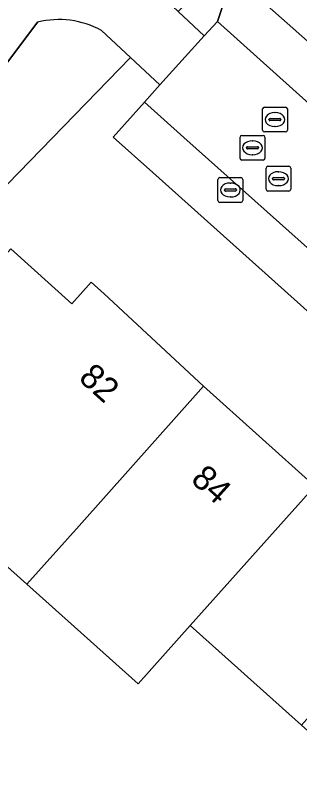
# Model space of a CAD drawing. Extents: x 159039 to 160102, y 381214 to 382524.
# Drawn here: x 159476.76 to 159488.23, y 381770.5 to 381801.71 of the extents above; entities that cross this region are included whole.
import ezdxf

# ---------------------------------------------------------------- set-up
doc = ezdxf.new("R2010")
doc.units = 0
for name, color, linetype in [('IMGEO_Brandkraan', 7, 'Continuous'), ('IMGEO_Erf', 7, 'Continuous'), ('IMGEO_Groenvoorziening', 7, 'Continuous'), ('IMGEO_Pand', 7, 'Continuous'), ('IMGEO_Pand_nummerreeks', 7, 'Continuous'), ('IMGEO_Rijbaan_lokaal_open', 7, 'Continuous'), ('IMGEO_Rioolput', 7, 'Continuous'), ('IMGEO_Voetpad_gesloten', 7, 'Continuous'), ('IMGEO_Voetpad_open', 7, 'Continuous')]:
    doc.layers.add(name, color=color, linetype=linetype)

msp = doc.modelspace()

# ---------------------------------------------------------------- linework, layer by layer
at = {"layer": 'IMGEO_Brandkraan'}
for p, q in [((159484.937, 381794.247), (159484.937, 381795.099)), ((159485.012, 381795.173), (159485.864, 381795.173)), ((159485.425, 381794.953), (159485.45, 381794.953)), ((159485.938, 381795.099), (159485.938, 381794.247)), ((159485.196, 381794.667), (159485.196, 381794.679)), ((159485.634, 381794.63), (159485.236, 381794.63)), ((159485.239, 381794.716), (159485.637, 381794.716)), ((159485.68, 381794.679), (159485.68, 381794.667)), ((159485.448, 381794.393), (159485.423, 381794.393)), ((159485.864, 381794.173), (159485.012, 381794.173))]:
    msp.add_line(p, q, dxfattribs=at)
for points in [[(159484.937, 381794.247), (159484.937, 381795.099)], [(159485.012, 381795.173), (159485.864, 381795.173)], [(159485.938, 381795.099), (159485.938, 381794.247)], [(159485.864, 381794.173), (159485.012, 381794.173)]]:
    msp.add_lwpolyline(points, dxfattribs=at)
for centre, radius, start, end in [((159485.014, 381795.097), 0.0765, 91.552, 178.448), ((159485.014, 381795.097), 0.0765, 91.552, 178.448), ((159485.862, 381795.097), 0.0765, 1.552, 88.448), ((159485.862, 381795.097), 0.0765, 1.552, 88.448), ((159485.236, 381794.676), 0.0403, 85.8775, 175.7526), ((159485.233, 381794.666), 0.0366, 178.938, 274.7102), ((159485.637, 381794.673), 0.043, 264.8664, 352.4533), ((159485.641, 381794.678), 0.0386, 1.7309, 96.639), ((159485.014, 381794.249), 0.0765, 181.552, 268.448), ((159485.014, 381794.249), 0.0765, 181.552, 268.448), ((159485.862, 381794.249), 0.0765, 271.552, 358.448), ((159485.862, 381794.249), 0.0765, 271.552, 358.448)]:
    msp.add_arc(centre, radius, start, end, dxfattribs=at)
for centre, major_axis, ratio, start_param, end_param in [((159485.424, 381794.673), (-0.387, 0.002), 0.722429, 4.712389, 7.853982), ((159485.449, 381794.673), (-0.39, 0.002), 0.717154, 1.570796, 4.712389)]:
    msp.add_ellipse(centre, major_axis=major_axis, ratio=ratio, start_param=start_param, end_param=end_param, dxfattribs=at)
at = {"layer": 'IMGEO_Erf'}
for points in [[(159501.065, 381796.188), (159500, 381797.141), (159496.559, 381800.223), (159491.947, 381804.353), (159492.348, 381804.8), (159489.145, 381807.669), (159485.386, 381803.473), (159485.533, 381803.343), (159487.723, 381801.404), (159503.573, 381787.369), (159506.301, 381784.953)], [(159500.454, 381779.131), (159482.304, 381795.376), (159480.705, 381796.807), (159481.965, 381798.214), (159482.586, 381798.907), (159481.405, 381800.01), (159470.575, 381788.888), (159462.202, 381778.537), (159461.61, 381777.805), (159456.183, 381771.095), (159456.944, 381770.48)], [(159473.576, 381783.985), (159474.721, 381785.263), (159472.259, 381787.467), (159476.579, 381792.296), (159479.045, 381790.089), (159479.818, 381790.953), (159480.34, 381790.486), (159484.353, 381786.758), (159488.841, 381782.739), (159493.329, 381778.719), (159497.93, 381774.598), (159500.688, 381777.572)], [(159477.218, 381778.778), (159473.981, 381781.672)], [(159492.904, 381768.986), (159488.306, 381773.102), (159483.817, 381777.121), (159481.709, 381774.763), (159477.218, 381778.778)]]:
    msp.add_lwpolyline(points, dxfattribs=at)
at = {"layer": 'IMGEO_Groenvoorziening'}
msp.add_lwpolyline([(159509.418, 381830.496), (159514.073, 381835.761), (159510.645, 381838.797), (159509.885, 381839.344), (159482.865, 381805.051), (159484.748, 381803.285), (159483.331, 381801.872), (159484.376, 381800.892), (159484.913, 381801.464), (159485.533, 381803.343), (159485.386, 381803.473), (159489.145, 381807.669), (159495.918, 381815.23), (159500, 381819.846)], close=True, dxfattribs=at)
for points in [[(159477.659, 381801.438), (159461.121, 381779.412), (159462.202, 381778.537), (159470.575, 381788.888)], [(159470.575, 381788.888), (159481.405, 381800.01), (159480.232, 381801.105)]]:
    msp.add_lwpolyline(points, dxfattribs=at)
msp.add_arc((159478.521, 381797.995), 3.55, 61.1903, 104.0611, dxfattribs=at)
at = {"layer": 'IMGEO_Pand'}
msp.add_lwpolyline([(159473.981, 381781.672), (159477.218, 381778.778), (159479.328, 381781.139), (159484.353, 381786.758), (159480.34, 381790.486), (159479.818, 381790.953), (159479.045, 381790.089), (159476.579, 381792.296), (159472.259, 381787.467), (159474.721, 381785.263), (159473.576, 381783.985)], dxfattribs=at)
for points in [[(159488.841, 381782.739), (159484.353, 381786.758), (159479.328, 381781.139), (159477.218, 381778.778), (159481.709, 381774.763), (159483.817, 381777.121)], [(159493.329, 381778.719), (159488.841, 381782.739), (159483.817, 381777.121), (159488.306, 381773.102)]]:
    msp.add_lwpolyline(points, close=True, dxfattribs=at)
at = {"layer": 'IMGEO_Rijbaan_lokaal_open'}
msp.add_lwpolyline([(159486.504, 381800.037), (159484.913, 381801.464), (159484.376, 381800.892), (159482.586, 381798.907), (159481.965, 381798.214), (159483.564, 381796.789), (159502.62, 381779.807), (159504.061, 381781.401), (159505.502, 381782.995)], close=True, dxfattribs=at)
at = {"layer": 'IMGEO_Rioolput'}
for p, q in [((159486.737, 381797.086), (159486.737, 381797.938)), ((159486.812, 381798.012), (159487.664, 381798.012)), ((159487.225, 381797.792), (159487.25, 381797.792)), ((159487.738, 381797.938), (159487.738, 381797.086)), ((159486.996, 381797.506), (159486.996, 381797.518)), ((159487.434, 381797.469), (159487.036, 381797.469)), ((159487.039, 381797.555), (159487.437, 381797.555)), ((159487.48, 381797.518), (159487.48, 381797.506)), ((159487.248, 381797.232), (159487.223, 381797.232)), ((159485.904, 381796.875), (159486.756, 381796.875)), ((159487.664, 381797.012), (159486.812, 381797.012)), ((159485.829, 381795.949), (159485.829, 381796.801)), ((159486.317, 381796.655), (159486.342, 381796.655)), ((159486.83, 381796.801), (159486.83, 381795.949)), ((159486.088, 381796.369), (159486.088, 381796.381)), ((159486.526, 381796.332), (159486.128, 381796.332)), ((159486.131, 381796.418), (159486.529, 381796.418)), ((159486.572, 381796.381), (159486.572, 381796.369)), ((159486.756, 381795.875), (159485.904, 381795.875)), ((159486.34, 381796.095), (159486.315, 381796.095)), ((159486.875, 381794.702), (159486.875, 381795.554)), ((159486.95, 381795.628), (159487.802, 381795.628)), ((159487.876, 381795.554), (159487.876, 381794.702)), ((159487.363, 381795.408), (159487.388, 381795.408)), ((159487.134, 381795.122), (159487.134, 381795.134)), ((159487.572, 381795.085), (159487.174, 381795.085)), ((159487.177, 381795.171), (159487.575, 381795.171)), ((159487.618, 381795.134), (159487.618, 381795.122)), ((159487.802, 381794.628), (159486.95, 381794.628)), ((159487.386, 381794.848), (159487.361, 381794.848))]:
    msp.add_line(p, q, dxfattribs=at)
for points in [[(159486.737, 381797.086), (159486.737, 381797.938)], [(159486.812, 381798.012), (159487.664, 381798.012)], [(159487.738, 381797.938), (159487.738, 381797.086)], [(159485.904, 381796.875), (159486.756, 381796.875)], [(159487.664, 381797.012), (159486.812, 381797.012)], [(159485.829, 381795.949), (159485.829, 381796.801)], [(159486.83, 381796.801), (159486.83, 381795.949)], [(159486.756, 381795.875), (159485.904, 381795.875)], [(159486.875, 381794.702), (159486.875, 381795.554)], [(159486.95, 381795.628), (159487.802, 381795.628)], [(159487.876, 381795.554), (159487.876, 381794.702)], [(159487.802, 381794.628), (159486.95, 381794.628)]]:
    msp.add_lwpolyline(points, dxfattribs=at)
for centre, radius, start, end in [((159486.814, 381797.936), 0.0765, 91.552, 178.448), ((159486.814, 381797.936), 0.0765, 91.552, 178.448), ((159487.662, 381797.936), 0.0765, 1.552, 88.448), ((159487.662, 381797.936), 0.0765, 1.552, 88.448), ((159487.036, 381797.515), 0.0403, 85.8775, 175.7526), ((159487.033, 381797.505), 0.0366, 178.938, 274.7102), ((159487.437, 381797.512), 0.043, 264.8664, 352.4533), ((159487.441, 381797.517), 0.0386, 1.7309, 96.639), ((159485.906, 381796.799), 0.0765, 91.552, 178.448), ((159485.906, 381796.799), 0.0765, 91.552, 178.448), ((159486.814, 381797.088), 0.0765, 181.552, 268.448), ((159486.814, 381797.088), 0.0765, 181.552, 268.448), ((159486.754, 381796.799), 0.0765, 1.552, 88.448), ((159486.754, 381796.799), 0.0765, 1.552, 88.448), ((159487.662, 381797.088), 0.0765, 271.552, 358.448), ((159487.662, 381797.088), 0.0765, 271.552, 358.448), ((159486.128, 381796.378), 0.0403, 85.8775, 175.7526), ((159486.125, 381796.368), 0.0366, 178.938, 274.7102), ((159486.529, 381796.375), 0.043, 264.8664, 352.4533), ((159486.533, 381796.38), 0.0386, 1.7309, 96.639), ((159485.906, 381795.951), 0.0765, 181.552, 268.448), ((159485.906, 381795.951), 0.0765, 181.552, 268.448), ((159486.754, 381795.951), 0.0765, 271.552, 358.448), ((159486.754, 381795.951), 0.0765, 271.552, 358.448), ((159486.952, 381795.552), 0.0765, 91.552, 178.448), ((159486.952, 381795.552), 0.0765, 91.552, 178.448), ((159487.8, 381795.552), 0.0765, 1.552, 88.448), ((159487.8, 381795.552), 0.0765, 1.552, 88.448), ((159487.174, 381795.131), 0.0403, 85.8775, 175.7526), ((159487.171, 381795.121), 0.0366, 178.938, 274.7102), ((159487.575, 381795.128), 0.043, 264.8664, 352.4533), ((159487.579, 381795.133), 0.0386, 1.7309, 96.639), ((159486.952, 381794.704), 0.0765, 181.552, 268.448), ((159486.952, 381794.704), 0.0765, 181.552, 268.448), ((159487.8, 381794.704), 0.0765, 271.552, 358.448), ((159487.8, 381794.704), 0.0765, 271.552, 358.448)]:
    msp.add_arc(centre, radius, start, end, dxfattribs=at)
for centre, major_axis, ratio, start_param, end_param in [((159487.224, 381797.512), (-0.387, 0.002), 0.722429, 4.712389, 7.853982), ((159487.249, 381797.512), (-0.39, 0.002), 0.717154, 1.570796, 4.712389), ((159486.316, 381796.375), (-0.387, 0.002), 0.722429, 4.712389, 7.853982), ((159486.341, 381796.375), (-0.39, 0.002), 0.717154, 1.570796, 4.712389), ((159487.362, 381795.128), (-0.387, 0.002), 0.722429, 4.712389, 7.853982), ((159487.387, 381795.128), (-0.39, 0.002), 0.717154, 1.570796, 4.712389)]:
    msp.add_ellipse(centre, major_axis=major_axis, ratio=ratio, start_param=start_param, end_param=end_param, dxfattribs=at)
at = {"layer": 'IMGEO_Voetpad_gesloten'}
for points in [[(159480.232, 381801.105), (159481.405, 381800.01), (159482.586, 381798.907), (159484.376, 381800.892), (159483.331, 381801.872), (159482.091, 381803.035)], [(159451.372, 381766.501), (159460.555, 381778.659), (159461.121, 381779.412), (159477.659, 381801.438)]]:
    msp.add_lwpolyline(points, dxfattribs=at)
msp.add_arc((159478.521, 381797.995), 3.55, 61.1903, 104.0611, dxfattribs=at)
at = {"layer": 'IMGEO_Voetpad_open'}
for points in [[(159487.723, 381801.404), (159485.533, 381803.343), (159484.913, 381801.464), (159486.504, 381800.037), (159505.502, 381782.995), (159507.718, 381785.16)], [(159506.301, 381784.953), (159503.573, 381787.369), (159487.723, 381801.404)], [(159483.564, 381796.789), (159481.965, 381798.214), (159480.705, 381796.807), (159482.304, 381795.376), (159500.454, 381779.131)], [(159500.688, 381777.572), (159502.62, 381779.807), (159483.564, 381796.789)]]:
    msp.add_lwpolyline(points, dxfattribs=at)

# ---------------------------------------------------------------- texts
at = {"layer": 'IMGEO_Pand_nummerreeks'}
for s, rotation, p in [('82', 317.9182, (159479.268, 381787.03)), ('84', 317.9162, (159483.797, 381782.939))]:
    msp.add_text(s, height=1, rotation=rotation, dxfattribs=at).set_placement(p)

doc.saveas('drawing.dxf')
